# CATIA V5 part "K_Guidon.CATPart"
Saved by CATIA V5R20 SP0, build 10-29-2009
Part number: Guidon
Bounding box of the stored display mesh (mm): x -375 to 375, y -19.997 to 19.997, z -15 to 180
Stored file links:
  G:\Khaled_CFAO_2011\ST2M\ST2M_GR1\bmartinez\Khaled\CAD_ThinkMOTION\K_Guidon.CATPart
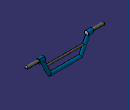
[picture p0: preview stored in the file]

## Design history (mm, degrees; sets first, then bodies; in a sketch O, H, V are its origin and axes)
Body1 (main body)
  Line1: stored without definition
  Point1: stored without definition
  Line2: stored without definition
  Sketch1 on zx-plane, origin (0, 0, 0), H (-1, 0, 0), V (0, 0, 1)
    point P1 (150, 0)
    line L1 (150, 0) -> (-150, 0)
    line L2 (-150, 0) -> (-150, 15)
    line L3 (-150, 15) -> (150, 15)
    line L4 (150, 15) -> (150, 0)
    reference projected point E1 (150, 0) from Point1
    reference projected line E2 (150, 0) -> (-150, 0) from Line2
    length L1 = 300
    length L4 = 15
    horizontal: L1 H, L3 H
    vertical: L2 V, L4 V
    coincidence: E1 P1, E2 L1
  Shaft1: profile Sketch1, axis Line1, angle 360
  Line3: stored without definition
  Line4: stored without definition
  Point2: stored without definition
  Point3: stored without definition
  Sketch2 on zx-plane, origin (0, 0, 0), H (-1, 0, 0), V (0, 0, 1)
    line L1 (163.5927, -6.3433) -> (233.5927, 143.6567)
    line L2 (233.5927, 143.6567) -> (220, 150)
    line L3 (220, 150) -> (150, 0)
    point P3 (220, 150)
    point P4 (150, 0)
    reference projected line E1 (220, 150) -> (150, 0) from Line4
    reference projected point E2 (150, 0) from Point2
    reference projected point E3 (220, 150) from Point3
    line L4 (163.5927, -6.3433) -> (150, -15)
    line L5 (150, -15) -> (150, 0)
    length L2 = 15
    length L5 = 15
    coincidence: L3 E1, E2 P4, P3 E3
    parallelism: L3 L1
    vertical: L5 V
  Shaft2: profile Sketch2, axis Sketch2.L3, angle 360
  Mirror1: of Shaft2, about yz-plane
  Line5 to Line7: stored without definition
  Sketch3 on zx-plane, origin (0, 0, 0), H (-1, 0, 0), V (0, 0, 1)
    point P1 (189.6519, 84.9683)
    line L1 (189.6519, 84.9683) -> (-185.9186, 84.9683)
    line L2 (-185.9186, 84.9683) -> (-185.9186, 76.9683)
    line L3 (-185.9186, 76.9683) -> (189.6519, 76.9683)
    line L4 (189.6519, 76.9683) -> (189.6519, 84.9683)
    point P3 (-185.9186, 76.9683)
    reference projected line E1 (220, 150) -> (150, 0) from Line6
    reference projected line E2 (-220, 150) -> (-150, 0) from Line7
    length L4 = 8
    horizontal: L1 H, L3 H
    vertical: L2 V, L4 V
    coincidence: P1 E1, P3 E2
  Shaft3: profile Sketch3, axis Sketch3.L1, angle 360
  Point4: stored without definition
  Sketch4 on zx-plane, origin (0, 0, 0), H (-1, 0, 0), V (0, 0, 1)
    line L1 (205, 160) -> (255, 160)
    line L2 (255, 160) -> (255, 140)
    line L3 (255, 140) -> (205, 140)
    line L4 (205, 140) -> (205, 160)
    reference projected point E1 (220, 150) from Point4
    length L2 = 20
    length L1 = 50
    distance L4 E1 = 15
    horizontal: L1 H, L3 H
    vertical: L2 V, L4 V
  Shaft4: profile Sketch4, axis Sketch4.L1, angle 360
  Sketch5 on face of Shaft4 from Sketch4.L2, origin (-255, 0, 0), H (0, -1, 0), V (0, 0, 1)
    circle A1 centre (0, 160) radius 14.1421
  Pad1: profile Sketch5, direction (-1, 0, 0), length 120
  Mirror2: of Shaft4, Pad1, about yz-plane
  Fillet1: radius 10, on edge [face of Mirror2 | face of Mirror2]; edge [face of Pad1 from Sketch5.A1 | end face of Pad1]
